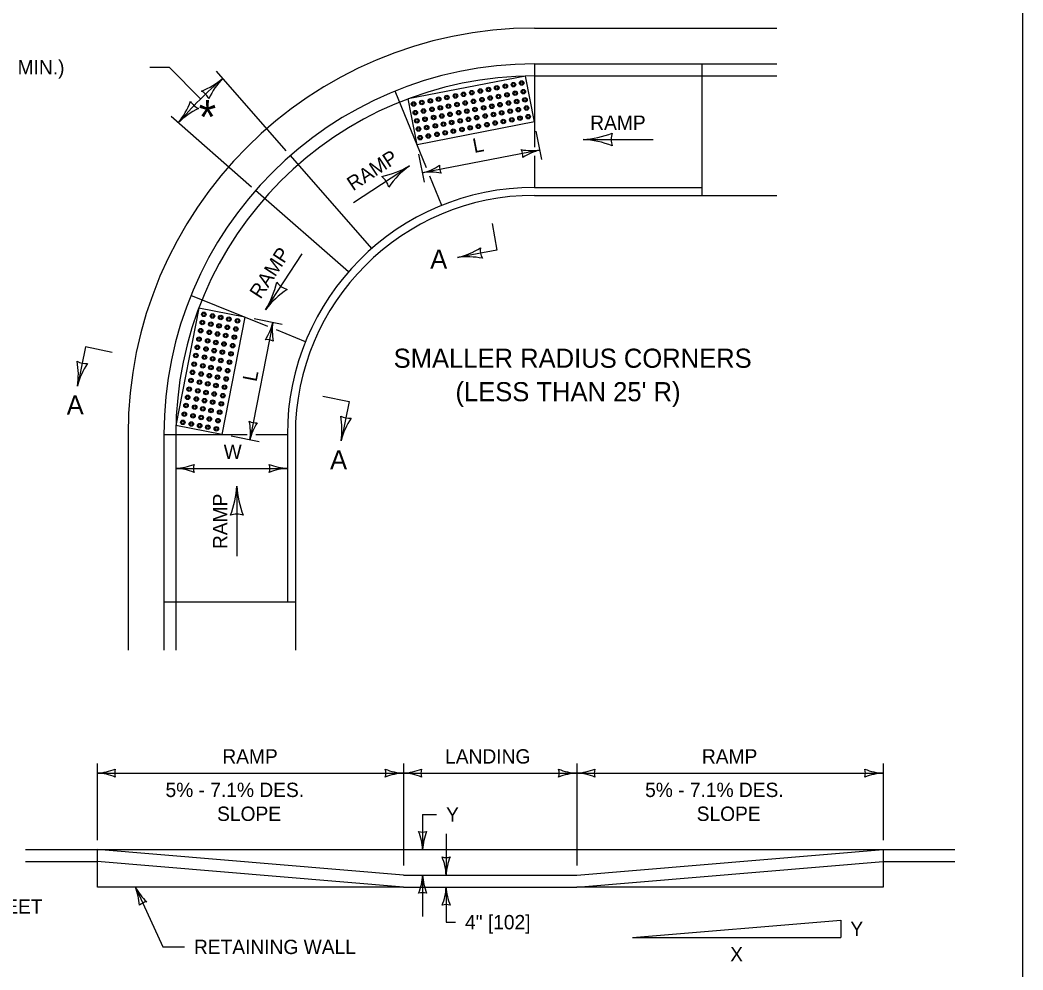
# Model space of a CAD drawing. Extents: x 49991.4 to 50021, y 49987.6 to 50011.4.
# Drawn here: x 50004.419 to 50008.615, y 50005.18 to 50009.154 of the extents above; entities that cross this region are included whole.
import ezdxf

# ---------------------------------------------------------------- set-up
doc = ezdxf.new("R2010")
doc.units = 0
for name, color, linetype in [('Level 1', 7, 'Continuous'), ('Level 2', 7, 'Continuous'), ('Level 3', 7, 'Continuous'), ('Level 4', 7, 'Continuous'), ('Level 6', 7, 'Continuous'), ('Level 8', 7, 'Continuous'), ('P_Dimensions_Styles_Eng', 7, 'Continuous')]:
    doc.layers.add(name, color=color, linetype=linetype)

msp = doc.modelspace()

# ---------------------------------------------------------------- linework, layer by layer
at = {"layer": 'Level 1'}
for p, q in [((50006.5705, 50009.1202), (50007.5845, 50009.1202)), ((50006.5705, 50008.9702), (50006.5705, 50008.6221)), ((50006.5705, 50008.9702), (50007.5845, 50008.9702)), ((50007.2705, 50008.9702), (50007.2705, 50008.4202)), ((50006.5705, 50008.9202), (50007.5845, 50008.9202)), ((50006.1186, 50008.5362), (50005.9887, 50008.8569)), ((50006.5705, 50008.7277), (50006.0798, 50008.6321)), ((50005.8902, 50008.198), (50005.5501, 50008.5869)), ((50006.5705, 50008.5855), (50006.5705, 50008.4535)), ((50006.1827, 50008.378), (50006.1327, 50008.5013)), ((50005.7928, 50008.1006), (50005.4039, 50008.4408)), ((50006.5705, 50008.4535), (50007.2705, 50008.4535)), ((50006.5705, 50008.4202), (50007.5845, 50008.4202)), ((50005.4551, 50007.872), (50005.1339, 50008.0021)), ((50005.3586, 50007.9111), (50005.263, 50007.4203)), ((50005.6128, 50007.8082), (50005.491, 50007.8575)), ((50004.8705, 50007.4203), (50004.8705, 50006.518)), ((50005.0205, 50007.4203), (50005.0205, 50006.518)), ((50005.0205, 50007.4203), (50005.3684, 50007.4202)), ((50005.0705, 50007.4203), (50005.0705, 50006.518)), ((50005.4046, 50007.4202), (50005.5372, 50007.4202)), ((50005.5372, 50007.4203), (50005.5372, 50006.7202)), ((50005.5705, 50007.4203), (50005.5705, 50006.518)), ((50005.0203, 50006.7203), (50005.5705, 50006.7202)), ((50004.4412, 50005.6832), (50008.3292, 50005.6832)), ((50006.0226, 50005.5764), (50004.7412, 50005.6832)), ((50006.7477, 50005.5764), (50008.0292, 50005.6832)), ((50004.4412, 50005.6332), (50004.7412, 50005.6332)), ((50006.0226, 50005.5264), (50004.7412, 50005.6332)), ((50006.7477, 50005.5264), (50008.0292, 50005.6332)), ((50008.0292, 50005.6332), (50008.3292, 50005.6332)), ((50006.0226, 50005.5764), (50006.7477, 50005.5764)), ((50006.0226, 50005.5264), (50006.7477, 50005.5264))]:
    msp.add_line(p, q, dxfattribs=at)
msp.add_lwpolyline([(50008.6146, 50011.2628), (50000.3356, 50011.2628), (50000.3356, 50000.0624), (50008.6146, 50000.0624)], close=True, dxfattribs=at)
msp.add_lwpolyline([(50008.6146, 50000.0624), (50008.6146, 50011.2628)], dxfattribs=at)
for radius in [1.7, 1.55, 1.5, 1.0333, 1]:
    msp.add_arc((50006.5705, 50007.4202), radius, 89.9972, 179.9963, dxfattribs=at)
at = {"layer": 'Level 2'}
for centre in [(50006.2538, 50008.7663), (50006.288, 50008.773), (50006.3223, 50008.7797), (50005.2106, 50007.6662), (50005.2173, 50007.7005), (50005.204, 50007.632)]:
    msp.add_circle(centre, 0.00945, dxfattribs=at)
at = {"layer": 'Level 3'}
for p, q in [((50005.042, 50008.9563), (50005.174, 50008.8237)), ((50006.5331, 50008.9198), (50006.0424, 50008.8242)), ((50006.5705, 50008.7277), (50006.5331, 50008.9198)), ((50006.0798, 50008.6321), (50006.0424, 50008.8242)), ((50006.6011, 50008.571), (50006.5782, 50008.6884)), ((50006.1103, 50008.4754), (50006.0874, 50008.5929)), ((50006.5934, 50008.6102), (50006.1026, 50008.5146)), ((50005.1666, 50007.9485), (50005.071, 50007.4577)), ((50005.3586, 50007.9111), (50005.1666, 50007.9485)), ((50005.4761, 50007.8882), (50005.3805, 50007.3974)), ((50005.5154, 50007.8806), (50005.3979, 50007.9035)), ((50005.263, 50007.4203), (50005.071, 50007.4577)), ((50005.4198, 50007.3898), (50005.3026, 50007.4126)), ((50005.0705, 50007.2781), (50005.5372, 50007.2781)), ((50004.7412, 50006.0432), (50004.7412, 50005.7232)), ((50006.0226, 50006.0432), (50006.0226, 50005.6164)), ((50006.7477, 50006.0432), (50006.7477, 50005.6164)), ((50008.0292, 50006.0432), (50008.0292, 50005.7232)), ((50004.7412, 50006.0032), (50006.0226, 50006.0032)), ((50006.0226, 50006.0032), (50006.7477, 50006.0032)), ((50006.7477, 50006.0032), (50008.0292, 50006.0032)), ((50006.103, 50005.83), (50006.1611, 50005.83)), ((50006.103, 50005.83), (50006.103, 50005.6832)), ((50006.2015, 50005.7498), (50006.2015, 50005.5764)), ((50006.103, 50005.5764), (50006.103, 50005.403)), ((50004.9013, 50005.5264), (50005.0167, 50005.2762)), ((50006.2015, 50005.5264), (50006.2015, 50005.3796)), ((50006.2015, 50005.3796), (50006.2406, 50005.3796)), ((50006.9816, 50005.3154), (50007.8521, 50005.3879)), ((50007.8526, 50005.3879), (50007.8526, 50005.3154)), ((50006.9821, 50005.3154), (50007.8526, 50005.3154)), ((50005.0167, 50005.2762), (50005.1062, 50005.2762))]:
    msp.add_line(p, q, dxfattribs=at)
for centre, radius, start, end in [((50005.0647, 50009.1462), 0.3107, 291.4017, 310.6516), ((50005.4797, 50008.704), 0.2964, 135.8394, 156.0229), ((50005.143, 50008.7929), 0.073, 25.6177, 61.3401), ((50004.8533, 50008.9144), 0.2964, 320.0002, 340.1837), ((50005.1956, 50008.8502), 0.073, 209.7785, 245.5009), ((50005.2993, 50008.5035), 0.3107, 115.5625, 134.8124), ((50006.7599, 50009.0099), 0.3557, 272.3605, 292.544), ((50006.9797, 50008.6545), 0.0876, 162.1388, 197.8612), ((50006.7562, 50008.2821), 0.3728, 67.9228, 87.1727), ((50006.5595, 50008.8299), 0.2223, 258.6043, 278.7878), ((50006.4676, 50008.5854), 0.0548, 353.2871, 29.0095), ((50006.6497, 50008.3841), 0.233, 103.9756, 123.2254), ((50005.8591, 50008.8653), 0.3728, 281.2589, 300.5087), ((50006.2559, 50008.2552), 0.3557, 125.6965, 145.88), ((50006.0449, 50008.7404), 0.233, 284.3396, 303.5895), ((50006.138, 50008.2951), 0.2223, 78.9683, 99.1518), ((50006.2283, 50008.5402), 0.0548, 173.6511, 209.3735), ((50005.877, 50008.4314), 0.0876, 15.4749, 51.1972), ((50006.183, 50008.4496), 0.2964, 282.8703, 303.0538), ((50006.4171, 50008.1918), 0.073, 172.6486, 208.371), ((50006.2906, 50007.8527), 0.3107, 78.4326, 97.6825), ((50005.1446, 50008.1313), 0.3557, 327.7906, 347.9741), ((50005.562, 50008.1106), 0.0876, 217.5689, 253.2913), ((50005.7417, 50007.7153), 0.3728, 123.3529, 142.6028), ((50005.2597, 50007.9392), 0.2223, 326.5565, 346.74), ((50005.7068, 50007.8555), 0.233, 171.9278, 191.1776), ((50005.4519, 50007.7623), 0.0548, 61.2393, 96.9616), ((50004.3662, 50007.6711), 0.2964, 350.5715, 10.755), ((50004.6935, 50007.7899), 0.073, 240.3499, 276.0722), ((50004.9592, 50007.5441), 0.3107, 146.1339, 165.3837), ((50005.404, 50007.5235), 0.0548, 241.6033, 277.3256), ((50005.1496, 50007.4287), 0.233, 352.2918, 11.5416), ((50005.5972, 50007.3478), 0.2223, 146.9205, 167.104), ((50005.4693, 50007.4416), 0.2964, 350.6295, 10.813), ((50005.7965, 50007.5608), 0.073, 240.4078, 276.1302), ((50006.0625, 50007.3153), 0.3107, 146.1918, 165.4417), ((50005.059, 50007.5109), 0.233, 272.8273, 292.0772), ((50005.1987, 50007.2781), 0.0548, 162.1388, 197.8612), ((50005.5464, 50007.5003), 0.2223, 247.456, 267.6395), ((50005.409, 50007.2781), 0.0548, 342.1388, 17.8612), ((50005.0614, 50007.056), 0.2223, 67.456, 87.6395), ((50005.5487, 50007.0454), 0.233, 92.8273, 112.0772), ((50004.9535, 50007.2225), 0.3728, 337.9228, 357.1727), ((50005.6813, 50007.2188), 0.3557, 182.3605, 202.544), ((50005.3259, 50006.999), 0.0876, 72.1388, 107.8612), ((50004.7297, 50006.236), 0.233, 272.8273, 292.0772), ((50004.732, 50005.7811), 0.2223, 67.456, 87.6395), ((50004.8694, 50006.0032), 0.0548, 162.1388, 197.8612), ((50006.0317, 50006.2254), 0.2223, 247.456, 267.6395), ((50005.8944, 50006.0032), 0.0548, 342.1388, 17.8612), ((50006.0341, 50005.7705), 0.233, 92.8273, 112.0772), ((50006.0111, 50006.236), 0.233, 272.8273, 292.0772), ((50006.0134, 50005.7811), 0.2223, 67.456, 87.6395), ((50006.1508, 50006.0032), 0.0548, 162.1388, 197.8612), ((50006.7568, 50006.2254), 0.2223, 247.456, 267.6395), ((50006.6195, 50006.0032), 0.0548, 342.1388, 17.8612), ((50006.7592, 50005.7705), 0.233, 92.8273, 112.0772), ((50006.7362, 50006.236), 0.233, 272.8273, 292.0772), ((50006.7385, 50005.7811), 0.2223, 67.456, 87.6395), ((50006.8759, 50006.0032), 0.0548, 162.1388, 197.8612), ((50008.0383, 50006.2254), 0.2223, 247.456, 267.6395), ((50007.901, 50006.0032), 0.0548, 342.1388, 17.8612), ((50008.0407, 50005.7705), 0.233, 92.8273, 112.0772), ((50006.103, 50005.8114), 0.0548, 252.1388, 287.8612), ((50005.8703, 50005.6717), 0.233, 2.8273, 22.0772), ((50006.3251, 50005.674), 0.2223, 157.456, 177.6395), ((50006.2015, 50005.7046), 0.0548, 252.1388, 287.8612), ((50005.9687, 50005.5649), 0.233, 2.8273, 22.0772), ((50006.4236, 50005.5672), 0.2223, 157.456, 177.6395), ((50005.8808, 50005.5856), 0.2223, 337.456, 357.6395), ((50006.3357, 50005.5879), 0.233, 182.8273, 202.0772), ((50005.0992, 50005.6278), 0.2223, 207.1267, 227.3102), ((50004.6852, 50005.4394), 0.233, 2.6891, 21.9389), ((50006.103, 50005.4482), 0.0548, 72.1388, 107.8612), ((50005.9793, 50005.5356), 0.2223, 337.456, 357.6395), ((50006.4342, 50005.5379), 0.233, 182.8273, 202.0772), ((50004.955, 50005.41), 0.0548, 96.9051, 132.6274), ((50006.2015, 50005.3982), 0.0548, 72.1388, 107.8612)]:
    msp.add_arc(centre, radius, start, end, dxfattribs=at)
at = {"layer": 'Level 4'}
for p, q in [((50004.7412, 50005.6832), (50004.7412, 50005.5264)), ((50008.0292, 50005.6832), (50008.0292, 50005.5264)), ((50006.0226, 50005.5264), (50004.7429, 50005.5264)), ((50008.0292, 50005.5264), (50006.7477, 50005.5264))]:
    msp.add_line(p, q, dxfattribs=at)
at = {"layer": 'Level 6'}
for p, q in [((50006.7746, 50008.6545), (50007.0677, 50008.6545)), ((50005.8145, 50008.3911), (50006.0484, 50008.5441)), ((50006.3933, 50008.3026), (50006.414, 50008.1912)), ((50005.4456, 50007.9417), (50005.5991, 50008.1763)), ((50006.414, 50008.1912), (50006.2491, 50008.1606)), ((50004.6929, 50007.7867), (50004.6586, 50007.6225)), ((50004.8036, 50007.7636), (50004.6929, 50007.7867)), ((50005.6849, 50007.5807), (50005.7958, 50007.5576)), ((50005.7958, 50007.5576), (50005.7618, 50007.3934)), ((50005.3259, 50007.2041), (50005.3259, 50006.911))]:
    msp.add_line(p, q, dxfattribs=at)
at = {"layer": 'Level 8'}
for centre, radius in [((50006.4488, 50008.8772), 0.00945), ((50006.483, 50008.8838), 0.00945), ((50006.483, 50008.8838), 0.00525), ((50006.5173, 50008.8905), 0.00945), ((50006.5173, 50008.8905), 0.00525), ((50006.2402, 50008.8365), 0.00945), ((50006.2743, 50008.8433), 0.00945), ((50006.2743, 50008.8433), 0.00525), ((50006.3086, 50008.85), 0.00945), ((50006.3086, 50008.85), 0.00525), ((50006.3446, 50008.857), 0.00945), ((50006.3446, 50008.857), 0.00525), ((50006.3789, 50008.8637), 0.00945), ((50006.3789, 50008.8637), 0.00525), ((50006.4131, 50008.8703), 0.00945), ((50006.4131, 50008.8703), 0.00525), ((50006.4202, 50008.8343), 0.00945), ((50006.4488, 50008.8772), 0.00525), ((50006.4558, 50008.8411), 0.00945), ((50006.4558, 50008.8411), 0.00525), ((50006.4901, 50008.8478), 0.00945), ((50006.4901, 50008.8478), 0.00525), ((50006.5243, 50008.8544), 0.00945), ((50006.5243, 50008.8544), 0.00525), ((50006.0652, 50008.8026), 0.00945), ((50006.0652, 50008.8026), 0.00525), ((50006.0994, 50008.8092), 0.00945), ((50006.0994, 50008.8092), 0.00525), ((50006.1355, 50008.8163), 0.00945), ((50006.1355, 50008.8163), 0.00525), ((50006.1698, 50008.8229), 0.00945), ((50006.1698, 50008.8229), 0.00525), ((50006.204, 50008.8296), 0.00945), ((50006.204, 50008.8296), 0.00525), ((50006.211, 50008.7935), 0.00945), ((50006.2402, 50008.8365), 0.00525), ((50006.2471, 50008.8006), 0.00945), ((50006.2471, 50008.8006), 0.00525), ((50006.2813, 50008.8072), 0.00945), ((50006.2813, 50008.8072), 0.00525), ((50006.3156, 50008.8139), 0.00945), ((50006.3156, 50008.8139), 0.00525), ((50006.3517, 50008.8209), 0.00945), ((50006.3517, 50008.8209), 0.00525), ((50006.3859, 50008.8276), 0.00945), ((50006.3859, 50008.8276), 0.00525), ((50006.3926, 50008.7933), 0.00945), ((50006.4202, 50008.8343), 0.00525), ((50006.4268, 50008.8), 0.00945), ((50006.4268, 50008.8), 0.00525), ((50006.4625, 50008.8068), 0.00945), ((50006.4625, 50008.8068), 0.00525), ((50006.4967, 50008.8135), 0.00945), ((50006.4967, 50008.8135), 0.00525), ((50006.531, 50008.8202), 0.00945), ((50006.531, 50008.8202), 0.00525), ((50006.0722, 50008.7665), 0.00945), ((50006.0722, 50008.7665), 0.00525), ((50006.1065, 50008.7732), 0.00945), ((50006.1065, 50008.7732), 0.00525), ((50006.1425, 50008.7802), 0.00945), ((50006.1425, 50008.7802), 0.00525), ((50006.1768, 50008.7869), 0.00945), ((50006.1768, 50008.7869), 0.00525), ((50006.1834, 50008.7526), 0.00945), ((50006.211, 50008.7935), 0.00525), ((50006.2177, 50008.7593), 0.00945), ((50006.2177, 50008.7593), 0.00525), ((50006.2538, 50008.7663), 0.00525), ((50006.288, 50008.773), 0.00525), ((50006.3223, 50008.7797), 0.00525), ((50006.3583, 50008.7867), 0.00945), ((50006.3583, 50008.7867), 0.00525), ((50006.365, 50008.7524), 0.00945), ((50006.3926, 50008.7933), 0.00525), ((50006.3993, 50008.7591), 0.00945), ((50006.3993, 50008.7591), 0.00525), ((50006.4335, 50008.7658), 0.00945), ((50006.4335, 50008.7658), 0.00525), ((50006.4692, 50008.7726), 0.00945), ((50006.4692, 50008.7726), 0.00525), ((50006.5034, 50008.7793), 0.00945), ((50006.5034, 50008.7793), 0.00525), ((50006.5377, 50008.7859), 0.00945), ((50006.5377, 50008.7859), 0.00525), ((50006.0789, 50008.7322), 0.00945), ((50006.0789, 50008.7322), 0.00525), ((50006.1131, 50008.7389), 0.00945), ((50006.1131, 50008.7389), 0.00525), ((50006.1492, 50008.7459), 0.00945), ((50006.1492, 50008.7459), 0.00525), ((50006.1559, 50008.7117), 0.00945), ((50006.1834, 50008.7526), 0.00525), ((50006.1901, 50008.7184), 0.00945), ((50006.1901, 50008.7184), 0.00525), ((50006.2244, 50008.725), 0.00945), ((50006.2244, 50008.725), 0.00525), ((50006.2604, 50008.7321), 0.00945), ((50006.2604, 50008.7321), 0.00525), ((50006.2947, 50008.7387), 0.00945), ((50006.2947, 50008.7387), 0.00525), ((50006.3289, 50008.7454), 0.00945), ((50006.3289, 50008.7454), 0.00525), ((50006.336, 50008.7093), 0.00945), ((50006.365, 50008.7524), 0.00525), ((50006.372, 50008.7164), 0.00945), ((50006.372, 50008.7164), 0.00525), ((50006.4063, 50008.723), 0.00945), ((50006.4063, 50008.723), 0.00525), ((50006.4405, 50008.7297), 0.00945), ((50006.4405, 50008.7297), 0.00525), ((50006.4762, 50008.7365), 0.00945), ((50006.4762, 50008.7365), 0.00525), ((50006.5104, 50008.7432), 0.00945), ((50006.5104, 50008.7432), 0.00525), ((50006.5447, 50008.7499), 0.00945), ((50006.5447, 50008.7499), 0.00525), ((50006.0856, 50008.698), 0.00945), ((50006.0856, 50008.698), 0.00525), ((50006.1198, 50008.7047), 0.00945), ((50006.1198, 50008.7047), 0.00525), ((50006.1268, 50008.6686), 0.00945), ((50006.1559, 50008.7117), 0.00525), ((50006.1629, 50008.6756), 0.00945), ((50006.1629, 50008.6756), 0.00525), ((50006.1971, 50008.6823), 0.00945), ((50006.1971, 50008.6823), 0.00525), ((50006.2314, 50008.689), 0.00945), ((50006.2314, 50008.689), 0.00525), ((50006.2675, 50008.696), 0.00945), ((50006.2675, 50008.696), 0.00525), ((50006.3017, 50008.7027), 0.00945), ((50006.3017, 50008.7027), 0.00525), ((50006.336, 50008.7093), 0.00525), ((50006.0926, 50008.6619), 0.00945), ((50006.0926, 50008.6619), 0.00525), ((50006.1268, 50008.6686), 0.00525), ((50005.1878, 50007.9229), 0.00945), ((50005.1878, 50007.9229), 0.00525), ((50005.2238, 50007.9158), 0.00945), ((50005.2238, 50007.9158), 0.00525), ((50005.1811, 50007.8886), 0.00945), ((50005.1811, 50007.8886), 0.00525), ((50005.2172, 50007.8816), 0.00945), ((50005.2172, 50007.8816), 0.00525), ((50005.2514, 50007.8749), 0.00945), ((50005.2514, 50007.8749), 0.00525), ((50005.2581, 50007.9092), 0.00945), ((50005.2581, 50007.9092), 0.00525), ((50005.2924, 50007.9025), 0.00945), ((50005.2924, 50007.9025), 0.00525), ((50005.3284, 50007.8955), 0.00945), ((50005.3284, 50007.8955), 0.00525), ((50005.1744, 50007.8543), 0.00945), ((50005.1744, 50007.8543), 0.00525), ((50005.2105, 50007.8473), 0.00945), ((50005.2105, 50007.8473), 0.00525), ((50005.2448, 50007.8406), 0.00945), ((50005.2448, 50007.8406), 0.00525), ((50005.279, 50007.834), 0.00945), ((50005.279, 50007.834), 0.00525), ((50005.2857, 50007.8682), 0.00945), ((50005.2857, 50007.8682), 0.00525), ((50005.3151, 50007.8269), 0.00945), ((50005.3217, 50007.8612), 0.00945), ((50005.3217, 50007.8612), 0.00525), ((50005.1674, 50007.8188), 0.00945), ((50005.1674, 50007.8188), 0.00525), ((50005.2034, 50007.8117), 0.00945), ((50005.2034, 50007.8117), 0.00525), ((50005.2377, 50007.8051), 0.00945), ((50005.2377, 50007.8051), 0.00525), ((50005.2719, 50007.7984), 0.00945), ((50005.2719, 50007.7984), 0.00525), ((50005.308, 50007.7914), 0.00945), ((50005.308, 50007.7914), 0.00525), ((50005.3151, 50007.8269), 0.00525), ((50005.154, 50007.7503), 0.00945), ((50005.154, 50007.7503), 0.00525), ((50005.1607, 50007.7845), 0.00945), ((50005.1607, 50007.7845), 0.00525), ((50005.1901, 50007.7432), 0.00945), ((50005.1968, 50007.7775), 0.00945), ((50005.1968, 50007.7775), 0.00525), ((50005.231, 50007.7708), 0.00945), ((50005.231, 50007.7708), 0.00525), ((50005.2653, 50007.7641), 0.00945), ((50005.2653, 50007.7641), 0.00525), ((50005.3013, 50007.7571), 0.00945), ((50005.3013, 50007.7571), 0.00525), ((50005.147, 50007.7142), 0.00945), ((50005.147, 50007.7142), 0.00525), ((50005.1831, 50007.7072), 0.00945), ((50005.1831, 50007.7072), 0.00525), ((50005.1901, 50007.7432), 0.00525), ((50005.2243, 50007.7366), 0.00945), ((50005.2243, 50007.7366), 0.00525), ((50005.2586, 50007.7299), 0.00945), ((50005.2586, 50007.7299), 0.00525), ((50005.2947, 50007.7229), 0.00945), ((50005.2947, 50007.7229), 0.00525), ((50005.1403, 50007.6799), 0.00945), ((50005.1403, 50007.6799), 0.00525), ((50005.1764, 50007.6729), 0.00945), ((50005.1764, 50007.6729), 0.00525), ((50005.2106, 50007.6662), 0.00525), ((50005.2173, 50007.7005), 0.00525), ((50005.2449, 50007.6596), 0.00945), ((50005.2516, 50007.6938), 0.00945), ((50005.2516, 50007.6938), 0.00525), ((50005.2876, 50007.6868), 0.00945), ((50005.2876, 50007.6868), 0.00525), ((50005.1338, 50007.6457), 0.00945), ((50005.1338, 50007.6457), 0.00525), ((50005.1697, 50007.6387), 0.00945), ((50005.1697, 50007.6387), 0.00525), ((50005.204, 50007.632), 0.00525), ((50005.2382, 50007.6253), 0.00945), ((50005.2382, 50007.6253), 0.00525), ((50005.2449, 50007.6596), 0.00525), ((50005.2743, 50007.6183), 0.00945), ((50005.281, 50007.6525), 0.00945), ((50005.281, 50007.6525), 0.00525), ((50005.1199, 50007.5754), 0.00945), ((50005.1266, 50007.6096), 0.00945), ((50005.1266, 50007.6096), 0.00525), ((50005.1627, 50007.6026), 0.00945), ((50005.1627, 50007.6026), 0.00525), ((50005.1969, 50007.5959), 0.00945), ((50005.1969, 50007.5959), 0.00525), ((50005.2312, 50007.5892), 0.00945), ((50005.2312, 50007.5892), 0.00525), ((50005.2673, 50007.5822), 0.00945), ((50005.2673, 50007.5822), 0.00525), ((50005.2743, 50007.6183), 0.00525), ((50005.1133, 50007.5411), 0.00945), ((50005.1133, 50007.5411), 0.00525), ((50005.1199, 50007.5754), 0.00525), ((50005.1493, 50007.5341), 0.00945), ((50005.156, 50007.5683), 0.00945), ((50005.156, 50007.5683), 0.00525), ((50005.1903, 50007.5617), 0.00945), ((50005.1903, 50007.5617), 0.00525), ((50005.2245, 50007.555), 0.00945), ((50005.2245, 50007.555), 0.00525), ((50005.2606, 50007.548), 0.00945), ((50005.2606, 50007.548), 0.00525), ((50005.1062, 50007.505), 0.00945), ((50005.1062, 50007.505), 0.00525), ((50005.1423, 50007.498), 0.00945), ((50005.1423, 50007.498), 0.00525), ((50005.1493, 50007.5341), 0.00525), ((50005.1766, 50007.4913), 0.00945), ((50005.1836, 50007.5274), 0.00945), ((50005.1836, 50007.5274), 0.00525), ((50005.2178, 50007.5207), 0.00945), ((50005.2178, 50007.5207), 0.00525), ((50005.2539, 50007.5137), 0.00945), ((50005.2539, 50007.5137), 0.00525), ((50005.0996, 50007.4708), 0.00945), ((50005.0996, 50007.4708), 0.00525), ((50005.1356, 50007.4638), 0.00945), ((50005.1356, 50007.4638), 0.00525), ((50005.1699, 50007.4571), 0.00945), ((50005.1699, 50007.4571), 0.00525), ((50005.1766, 50007.4913), 0.00525), ((50005.2041, 50007.4504), 0.00945), ((50005.2108, 50007.4847), 0.00945), ((50005.2108, 50007.4847), 0.00525), ((50005.2469, 50007.4776), 0.00945), ((50005.2469, 50007.4776), 0.00525), ((50005.2041, 50007.4504), 0.00525), ((50005.2402, 50007.4434), 0.00945), ((50005.2402, 50007.4434), 0.00525)]:
    msp.add_circle(centre, radius, dxfattribs=at)
at = {"layer": 'P_Dimensions_Styles_Eng'}
for p, q in [((50004.962, 50008.9563), (50005.042, 50008.9563)), ((50005.5324, 50008.6071), (50005.2407, 50008.9406)), ((50005.3875, 50008.4551), (50005.0503, 50008.7502))]:
    msp.add_line(p, q, dxfattribs=at)
msp.add_arc((50006.5705, 50007.4202), 1.9798, 131.1741, 138.8194, dxfattribs=at)

# ---------------------------------------------------------------- texts
at = {"layer": 'Level 2'}
for s, height, p in [('RAMP', 0.06, (50006.8042, 50008.6945)), ('SMALLER RADIUS CORNERS', 0.08, (50005.9818, 50007.6991)), ("(LESS THAN 25' R)", 0.08, (50006.2403, 50007.5591)), ('W', 0.06, (50005.2706, 50007.3181)), ('RAMP', 0.06, (50005.265, 50006.0432)), ('LANDING', 0.06, (50006.1971, 50006.0432)), ('RAMP', 0.06, (50007.2715, 50006.0432)), ('5% - 7.1% DES.', 0.06, (50005.0274, 50005.9032)), ('5% - 7.1% DES.', 0.06, (50007.0339, 50005.9032)), ('SLOPE', 0.06, (50005.2431, 50005.8032)), ('Y', 0.06, (50006.2011, 50005.8)), ('SLOPE', 0.06, (50007.2496, 50005.8032)), ('STREET', 0.06, (50004.1962, 50005.4149)), ('4" [102]', 0.06, (50006.2805, 50005.3496)), ('Y', 0.06, (50007.8926, 50005.3216)), ('RETAINING WALL', 0.06, (50005.1462, 50005.2462)), ('X', 0.06, (50007.3898, 50005.2154))]:
    msp.add_text(s, height=height, dxfattribs=at).set_placement(p)
for s, height, rotation, p in [('L', 0.06, 10.9734, (50006.319, 50008.5975)), ('RAMP', 0.06, 33.3283, (50005.8118, 50008.4368)), ('RAMP', 0.06, 56.9027, (50005.425, 50007.983)), ('A', 0.08, 359.5801, (50006.1347, 50008.1138)), ('L', 0.06, 78.9256, (50005.408, 50007.6381)), ('A', 0.08, 0.7945, (50004.6141, 50007.5029)), ('A', 0.08, 359.5801, (50005.7157, 50007.2745)), ('RAMP', 0.06, 90.0825, (50005.286, 50006.9407))]:
    msp.add_text(s, height=height, rotation=rotation, dxfattribs=at).set_placement(p)
at = {"layer": 'Level 3'}
msp.add_text('*', height=0.14, dxfattribs=at).set_placement((50005.1661, 50008.6789))
at = {"layer": 'P_Dimensions_Styles_Eng'}
msp.add_text('3\' [914] DES.  (6" [152] MIN.)', height=0.06, dxfattribs=at).set_placement((50003.5709, 50008.9263))

doc.saveas('drawing.dxf')
